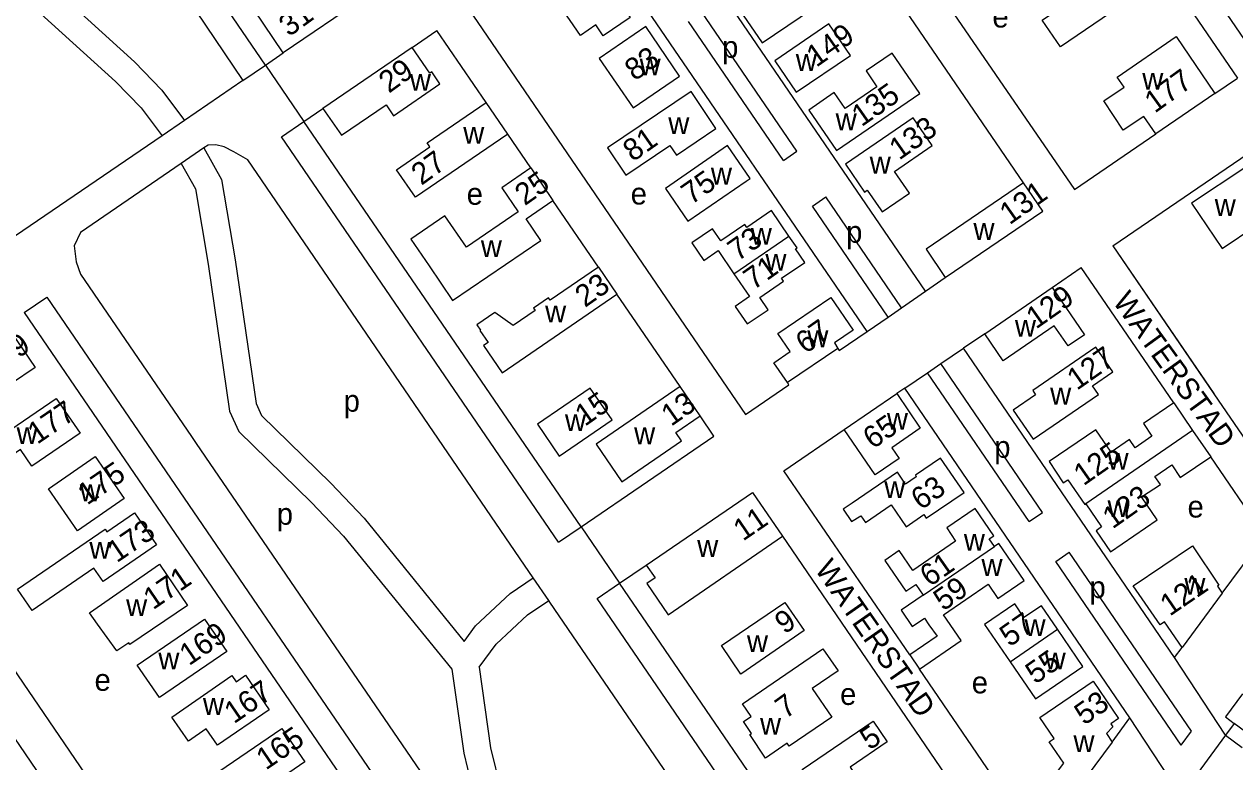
# Model space of a CAD drawing. Extents: x 154320 to 156262, y 382651 to 384180.
# Drawn here: x 155553.7 to 155775.5, y 383279.2 to 383414.4 of the extents above; entities that cross this region are included whole.
import ezdxf

# ---------------------------------------------------------------- set-up
doc = ezdxf.new("R2010")
doc.units = 0
for name, color, linetype in [('BLT_Basislijn', 7, 'Continuous'), ('BLT_Bebouwing', 7, 'Continuous'), ('BLT_Centroide', 7, 'Continuous'), ('BLT_Huisnummer', 7, 'Continuous'), ('BLT_Onderdoorgang_en_onderverdeling', 7, 'Continuous'), ('BLT_Onderverdeling_panden', 7, 'Continuous'), ('BLT_Straatnaam', 7, 'Continuous'), ('BLT_Vlakafsluiter', 7, 'Continuous')]:
    doc.layers.add(name, color=color, linetype=linetype)

msp = doc.modelspace()

# ---------------------------------------------------------------- linework, layer by layer
at = {"layer": 'BLT_Basislijn'}
for p, q in [((155556.64, 383458.99), (155593.76, 383404.06)), ((155695.34, 383458.35), (155746.12, 383384.05)), ((155736.8, 383385.3), (155689.56, 383454.4)), ((155718.85, 383365.44), (155668.08, 383439.72)), ((155708.13, 383358.08), (155657.35, 383432.39)), ((155635.07, 383417.16), (155685.86, 383342.86)), ((155692.79, 383389.39), (155675.38, 383414.87)), ((155695.26, 383391.09), (155677.85, 383416.57)), ((155624.76, 383410.11), (155629.29, 383413.21)), ((155638.32, 383400), (155629.29, 383413.21)), ((155597.88, 383406.88), (155601.13, 383409.09)), ((155593.76, 383404.06), (155597.88, 383406.88)), ((155593.76, 383404.06), (155583.05, 383396.74)), ((155771.89, 383401.67), (155776.01, 383404.48)), ((155604.94, 383396.56), (155608.42, 383398.94)), ((155583.05, 383396.74), (155578.92, 383393.92)), ((155600.81, 383393.74), (155604.94, 383396.56)), ((155646.52, 383388.04), (155642.27, 383394.22)), ((155746.12, 383384.05), (155761.04, 383394.24)), ((155753.18, 383373.73), (155783.06, 383394.16)), ((155586.6, 383391.69), (155582.46, 383388.85)), ((155692.79, 383389.39), (155695.26, 383391.09)), ((155658.91, 383369.87), (155650.54, 383382.07)), ((155698.11, 383381.01), (155700.59, 383382.7)), ((155714.46, 383362.41), (155700.59, 383382.7)), ((155711.98, 383360.71), (155698.11, 383381.01)), ((155742.04, 383366.09), (155747.4, 383369.78)), ((155764.34, 383344.99), (155747.4, 383369.78)), ((155718.85, 383365.44), (155722.45, 383367.93)), ((155553.66, 383361.51), (155557.79, 383364.33)), ((155673.9, 383347.96), (155662.3, 383364.91)), ((155714.46, 383362.41), (155718.85, 383365.44)), ((155711.98, 383360.71), (155714.46, 383362.41)), ((155708.13, 383358.08), (155711.98, 383360.71)), ((155729.69, 383357.65), (155725.79, 383355)), ((155721.66, 383352.19), (155725.79, 383355)), ((155764.5, 383298.35), (155725.79, 383355)), ((155715.05, 383347.68), (155719.18, 383350.49)), ((155719.18, 383350.49), (155721.66, 383352.19)), ((155737.82, 383323.22), (155719.18, 383350.49)), ((155740.3, 383324.91), (155721.66, 383352.19)), ((155715.05, 383347.68), (155713.56, 383346.67)), ((155756.32, 383287.28), (155715.05, 383347.68)), ((155772.5, 383345.46), (155785.39, 383326.61)), ((155680.08, 383338.91), (155677.56, 383342.59)), ((155521.89, 383339.79), (155585.65, 383246.5)), ((155692.91, 383332.54), (155703.92, 383340.08)), ((155655.72, 383322.26), (155680.08, 383338.91)), ((155516.11, 383335.84), (155555.91, 383277.62)), ((155780.99, 383320.63), (155771.12, 383335.1)), ((155715.98, 383298.81), (155692.91, 383332.54)), ((155737.82, 383323.22), (155740.3, 383324.91)), ((155651.6, 383319.44), (155655.72, 383322.26)), ((155692.64, 383320.53), (155725.53, 383272.42)), ((155773.24, 383310.1), (155780.99, 383320.63)), ((155742.71, 383315.9), (155745.19, 383317.6)), ((155767.6, 383284.81), (155745.19, 383317.6)), ((155662.78, 383311.94), (155667.63, 383315.26)), ((155765.7, 383282.27), (155742.71, 383315.9)), ((155649.79, 383308.8), (155646.96, 383312.92)), ((155658.65, 383309.12), (155662.78, 383311.94)), ((155764.5, 383298.35), (155765.88, 383300.16)), ((155773.85, 383284.08), (155764.5, 383298.35)), ((155734.58, 383271.59), (155717.76, 383296.2)), ((155753.04, 383282.83), (155756.32, 383287.28)), ((155765.68, 383273), (155756.32, 383287.28)), ((155765.7, 383282.27), (155767.6, 383284.81))]:
    msp.add_line(p, q, dxfattribs=at)
for points in [[(155473.87, 383522.91), (155483.98, 383497.86), (155486.36, 383493.38), (155496.62, 383477.01), (155506.99, 383465.16), (155518.91, 383453.74), (155544.48, 383433.68), (155554.14, 383425.4), (155573.89, 383407.44), (155578.88, 383402.26), (155583.05, 383396.74)], [(155724.46, 383488.76), (155778.83, 383409.21)], [(155725.22, 383478.78), (155776.01, 383404.48)], [(155597.88, 383406.88), (155561.52, 383460.08)], [(155541.74, 383429.44), (155550.83, 383421.65), (155570.4, 383403.86), (155575.07, 383399.01), (155578.92, 383393.92)], [(155655.72, 383322.26), (155604.94, 383396.56)], [(155578.92, 383393.92), (155550.74, 383374.65)], [(155651.6, 383319.44), (155600.81, 383393.74)], [(155609.37, 383367.92), (155594.62, 383389.51), (155592.08, 383390.99), (155590.31, 383391.9), (155588.78, 383392.23), (155587.35, 383392.2), (155586.6, 383391.69)], [(155586.6, 383391.69), (155589.84, 383385.89), (155592.33, 383371.19), (155596.16, 383344.88), (155597.14, 383342.68), (155609.88, 383330.25), (155615.94, 383323.87), (155634.31, 383301.29), (155636.39, 383304.12), (155642.75, 383310.08), (155646.96, 383312.92)], [(155582.46, 383388.85), (155564.01, 383376.22), (155562.83, 383373.73), (155563.17, 383370.79), (155563.98, 383368.57), (155584.31, 383338.82)], [(155582.46, 383388.85), (155585.05, 383384.2), (155587.39, 383370.41), (155591.31, 383343.47), (155592.97, 383339.76), (155606.32, 383326.74), (155612.19, 383320.57), (155632.03, 383296.17)], [(155753.18, 383373.73), (155771.67, 383346.67)], [(155753.18, 383373.73), (155772.5, 383345.46)], [(155645.38, 383315.25), (155609.37, 383367.92)], [(155557.79, 383364.33), (155621.56, 383271.05)], [(155553.66, 383361.51), (155617.43, 383268.23)], [(155702.78, 383354.92), (155703, 383354.57), (155708.13, 383358.08)], [(155685.86, 383342.86), (155693.81, 383348.29), (155693.53, 383348.7)], [(155584.31, 383338.82), (155585.2, 383337.53)], [(155585.2, 383337.53), (155633.64, 383266.67)], [(155646.96, 383312.92), (155645.38, 383315.25)], [(155703.78, 383251.95), (155662.78, 383311.94)], [(155637.02, 383296.55), (155640.14, 383300.78), (155645.88, 383306.16), (155649.79, 383308.8)], [(155650, 383308.48), (155649.79, 383308.8)], [(155733.58, 383186.21), (155650, 383308.48)], [(155743.62, 383184.81), (155658.65, 383309.12)], [(155632.03, 383296.17), (155634.22, 383280.82), (155636.28, 383272.35), (155637.06, 383270.79)], [(155637.02, 383296.55), (155639.14, 383281.76), (155641.01, 383274.08), (155641.67, 383272.76), (155645.83, 383270.38), (155656.73, 383261.45), (155664.48, 383253), (155671.55, 383242.34)]]:
    msp.add_lwpolyline(points, dxfattribs=at)
at = {"layer": 'BLT_Bebouwing'}
for p, q in [((155616.31, 383419.44), (155601.13, 383409.09)), ((155771.89, 383401.67), (155761.04, 383394.24)), ((155642.27, 383394.22), (155638.32, 383400)), ((155646.52, 383388.04), (155650.54, 383382.07)), ((155658.91, 383369.87), (155662.3, 383364.91)), ((155729.69, 383357.65), (155742.04, 383366.09)), ((155551.17, 383358.09), (155555.66, 383351.45)), ((155555.66, 383351.45), (155551.36, 383348.55)), ((155677.56, 383342.59), (155673.9, 383347.96)), ((155703.92, 383340.08), (155713.56, 383346.67)), ((155764.34, 383344.99), (155767.79, 383339.94)), ((155767.79, 383339.94), (155771.12, 383335.1)), ((155667.63, 383315.26), (155687.13, 383328.59)), ((155565.61, 383306.49), (155578.47, 383315.46)), ((155578.47, 383315.46), (155583.56, 383307.88)), ((155773.24, 383310.1), (155765.88, 383300.16)), ((155567.09, 383304.46), (155565.61, 383306.49)), ((155583.56, 383307.88), (155573, 383300.73)), ((155570.66, 383299.53), (155567.09, 383304.46)), ((155715.98, 383298.81), (155717.76, 383296.2)), ((155775.43, 383286.24), (155773.85, 383284.08)), ((155773.85, 383284.08), (155765.68, 383273)), ((155753.04, 383282.83), (155739.44, 383264.48))]:
    msp.add_line(p, q, dxfattribs=at)
for points in [[(155697.78, 383427.86), (155693.81, 383425.08), (155695.35, 383422.82), (155685.43, 383416.04), (155688.91, 383410.93), (155702.86, 383420.43)], [(155740.22, 383415.12), (155755.49, 383425.56), (155758.85, 383420.64), (155743.58, 383410.2)], [(155667.56, 383413.91), (155659.05, 383408.1), (155665.26, 383399.02), (155673.76, 383404.83)], [(155705.07, 383408.64), (155701.13, 383414.42), (155691.22, 383407.67), (155695.17, 383401.89)], [(155717.79, 383401.63), (155712.71, 383409.05), (155707.95, 383405.8), (155709.95, 383402.87), (155704.13, 383398.91), (155704.1, 383398.89), (155702.11, 383401.82), (155697.45, 383398.62), (155702.54, 383391.19)], [(155675.88, 383402.02), (155660.55, 383391.69), (155663.91, 383386.71), (155671.99, 383392.15), (155673.18, 383390.39), (155680.41, 383395.26)], [(155716.61, 383397.2), (155704.19, 383388.7), (155707.66, 383383.61), (155708.18, 383383.97), (155710.67, 383380.33), (155710.91, 383379.98), (155715.91, 383383.4), (155713.19, 383387.4), (155720.09, 383392.12)], [(155671.17, 383384.28), (155671.17, 383384.28), (155675.29, 383378.29), (155685.96, 383385.61), (155686.69, 383386.11), (155682.57, 383392.11)], [(155777.52, 383388.19), (155767.61, 383381.54), (155773.21, 383373.26), (155785.57, 383381.57), (155781.34, 383387.77), (155778.94, 383386.11)], [(155750.04, 383355.17), (155738.52, 383347.23), (155739.02, 383346.48), (155734.93, 383343.67), (155738.59, 383338.35), (155750.54, 383346.53), (155749.46, 383348.09), (155753.15, 383350.64)], [(155651.7, 383335.24), (155661.39, 383341.85), (155657.41, 383347.68), (155647.72, 383341.06)], [(155559.55, 383345.79), (155563.92, 383339.45), (155555.04, 383333.38), (155552.97, 383336.41), (155548.57, 383333.47), (155546.31, 383336.79)], [(155725.91, 383328.55), (155721.58, 383334.86), (155716.98, 383331.73), (155717.16, 383331.46), (155715.16, 383330.09), (155713.69, 383332.26), (155705.4, 383326.62), (155703.74, 383325.49), (155705.29, 383323.22), (155706.97, 383324.31), (155707.84, 383323.04), (155712.57, 383326.27), (155715.27, 383322.29), (155718.54, 383324.52), (155718.99, 383323.85)], [(155552.46, 383310.85), (155568.52, 383321.84), (155568.52, 383321.84), (155568.83, 383321.38), (155573.89, 383324.84), (155577.93, 383318.97), (155568.15, 383312.27), (155566.45, 383314.72), (155555.11, 383306.97)], [(155681.48, 383300.53), (155693.05, 383308.42), (155696.61, 383303.25), (155684.99, 383295.29)], [(155578.45, 383291.01), (155574.38, 383296.93), (155586.72, 383305.37), (155590.81, 383299.42)], [(155700.05, 383299.93), (155702.81, 383295.89), (155698.07, 383292.65), (155701.66, 383287.4), (155693.88, 383282.08), (155693.51, 383282.62), (155689.55, 383279.91), (155686.62, 383284.21), (155686.95, 383284.43), (155685.48, 383286.58), (155686.88, 383287.54), (155685.3, 383289.85)], [(155580.71, 383287.42), (155591.71, 383295.01), (155592.49, 383293.88), (155594.25, 383295.08), (155598.54, 383288.77), (155589.08, 383282.24), (155587, 383285.26), (155583.8, 383283.03)], [(155693.07, 383274.69), (155696.7, 383277.17), (155696.26, 383277.81), (155709.26, 383286.67), (155711.83, 383282.87), (155705.05, 383278.22), (155707.15, 383275.12), (155697.37, 383268.44)], [(155588.19, 383276.62), (155600.89, 383285.34), (155605.09, 383279.22), (155592.39, 383270.5)]]:
    msp.add_lwpolyline(points, close=True, dxfattribs=at)
for points in [[(155601.13, 383409.09), (155595.78, 383416.98), (155604.04, 383422.64), (155606.48, 383419.06), (155613.38, 383423.78), (155616.31, 383419.44)], [(155659.87, 383422.81), (155664.73, 383415.61), (155659.79, 383412.24), (155658.41, 383414.23), (155655.62, 383412.27), (155651.85, 383417.77)], [(155761.04, 383394.24), (155758.84, 383397.45), (155755.09, 383394.96), (155751.53, 383400.31), (155755.26, 383402.79), (155753.97, 383404.67), (155764.79, 383412.11), (155771.89, 383401.67)], [(155624.76, 383410.11), (155608.42, 383398.94)], [(155611.8, 383394.01), (155619.97, 383399.59), (155621.34, 383397.59), (155629.86, 383403.42), (155628.37, 383405.61), (155628.01, 383405.36), (155624.76, 383410.11)], [(155771.89, 383401.67), (155761.04, 383394.24)], [(155642.27, 383394.22), (155642.27, 383394.22), (155625.35, 383382.65), (155621.9, 383387.69), (155628.01, 383391.86), (155627.51, 383392.61), (155638.32, 383400)], [(155608.42, 383398.94), (155611.8, 383394.01)], [(155646.52, 383388.04), (155641.2, 383384.4), (155644.21, 383379.98), (155634.7, 383373.48), (155630.74, 383379.26), (155624.5, 383374.99), (155627.86, 383370.1), (155632.18, 383363.75), (155632.18, 383363.75), (155648.35, 383374.74), (155645.64, 383378.69), (155650.54, 383382.07)], [(155736.8, 383385.3), (155718.99, 383373.13), (155722.45, 383367.93)], [(155722.45, 383367.93), (155740.35, 383380.13), (155736.8, 383385.3)], [(155693.82, 383375.52), (155690.62, 383380.2), (155686.08, 383377.1), (155685.71, 383377.64), (155681.36, 383374.67), (155679.83, 383376.89), (155676, 383374.29), (155678.21, 383371.08), (155680.83, 383372.87), (155683.71, 383368.64)], [(155683.71, 383368.64), (155686.57, 383364.44), (155683.96, 383362.65), (155686.16, 383359.44), (155689.99, 383362.04), (155688.46, 383364.27), (155692.81, 383367.26), (155692.45, 383367.81), (155696.71, 383370.71), (155695.03, 383373.19), (155695.3, 383373.37), (155693.82, 383375.52)], [(155658.91, 383369.87), (155650.05, 383363.81), (155649.77, 383364.23), (155647.01, 383362.35), (155647.01, 383362.35), (155647.3, 383361.93), (155643.29, 383359.18), (155639.89, 383361.52), (155636.64, 383359.3), (155637.28, 383358.33), (155637.15, 383358.24), (155638.67, 383356.03), (155637.85, 383355.47), (155641.23, 383350.51), (155662.3, 383364.91)], [(155742.04, 383366.09), (155747.96, 383357.43), (155744.99, 383355.41), (155742.45, 383359.1), (155733.06, 383352.69), (155729.69, 383357.65)], [(155693.53, 383348.7), (155691.05, 383352.33), (155694.05, 383354.38), (155691.79, 383357.69), (155701.47, 383364.31), (155705.58, 383358.3), (155702.14, 383355.95), (155702.78, 383354.92)], [(155702.78, 383354.92), (155693.53, 383348.7)], [(155673.9, 383347.96), (155658.48, 383337.4), (155663.19, 383330.53), (155674.13, 383338), (155673.08, 383339.53), (155677.56, 383342.59)], [(155713.56, 383346.67), (155717.88, 383340.32), (155712.69, 383336.77), (155714.02, 383334.81), (155709.6, 383331.78), (155703.92, 383340.08)], [(155764.34, 383344.99), (155758.77, 383341.19), (155760.35, 383338.87), (155757.25, 383336.75), (155756.22, 383338.25), (155752.85, 383335.92), (155750.04, 383340.05), (155741.48, 383334.21), (155744.09, 383330.33), (155744.92, 383330.89), (155748.04, 383326.35), (155748.21, 383326.47)], [(155558.12, 383329.25), (155566.67, 383335.16), (155571.98, 383327.47)], [(155748.21, 383326.47), (155751.11, 383322.24), (155750.11, 383321.55), (155752.75, 383317.69), (155761.32, 383323.56), (155758.45, 383327.74), (155761.89, 383330), (155760.87, 383331.48), (155763.97, 383333.6), (155765.54, 383331.29), (155771.12, 383335.1)], [(155571.98, 383327.47), (155563.41, 383321.56), (155558.12, 383329.25)], [(155687.13, 383328.59), (155692.64, 383320.53)], [(155731.48, 383318.66), (155730.51, 383320.08), (155731.34, 383320.63), (155727.94, 383325.61), (155722.73, 383322.06), (155724.37, 383319.65), (155716.52, 383314.29), (155716.52, 383314.29), (155714.03, 383317.92), (155711.38, 383316.1), (155715.23, 383310.48), (155717.05, 383311.73), (155718.41, 383309.74)], [(155667.63, 383315.26), (155669.27, 383312.93), (155667.8, 383311.9), (155671.69, 383306.17), (155692.64, 383320.53)], [(155717.76, 383296.2), (155725.38, 383301.43), (155722.14, 383306.17), (155730.3, 383311.75), (155732.08, 383309.16), (155736.95, 383312.44), (155732.3, 383319.22), (155731.48, 383318.66)], [(155765.88, 383300.16), (155762.66, 383304.86), (155761.82, 383304.29), (155756.92, 383311.46), (155767.79, 383318.76), (155772.62, 383311.57), (155772.35, 383311.39), (155773.24, 383310.1)], [(155718.41, 383309.74), (155714.37, 383307), (155716.43, 383304.03), (155718.64, 383305.54), (155719.46, 383304.34), (155720.97, 383302.21), (155715.98, 383298.81)], [(155743.04, 383303.5), (155740.09, 383307.82), (155736.89, 383305.65), (155735.2, 383308.16), (155729.68, 383304.39), (155734.33, 383297.56)], [(155734.33, 383297.56), (155738.98, 383290.74), (155747.68, 383296.68), (155743.04, 383303.5)], [(155573, 383300.73), (155572.84, 383301.01), (155570.66, 383299.53)], [(155734.58, 383271.59), (155742.87, 383277.18), (155744.17, 383279), (155741.52, 383282.89), (155742.43, 383283.52), (155739.81, 383287.34), (155749.57, 383293.99), (155754.23, 383287.14), (155752.82, 383286.19), (155753.19, 383285.64), (155751.99, 383284.39), (155753.04, 383282.83)], [(155776.95, 383291.65), (155773.82, 383287.43), (155775.43, 383286.24)]]:
    msp.add_lwpolyline(points, dxfattribs=at)
at = {"layer": 'BLT_Onderdoorgang_en_onderverdeling'}
msp.add_line((155773.85, 383284.08), (155776.89, 383281.82), dxfattribs=at)
at = {"layer": 'BLT_Onderverdeling_panden'}
for p, q in [((155683.71, 383368.64), (155693.82, 383375.52)), ((155767.79, 383339.94), (155748.21, 383326.47)), ((155718.41, 383309.74), (155731.48, 383318.66)), ((155734.33, 383297.56), (155743.04, 383303.5)), ((155783.51, 383280.27), (155775.43, 383286.24))]:
    msp.add_line(p, q, dxfattribs=at)
at = {"layer": 'BLT_Vlakafsluiter'}
for p, q in [((155597.88, 383406.88), (155604.94, 383396.56)), ((155655.72, 383322.26), (155662.78, 383311.94))]:
    msp.add_line(p, q, dxfattribs=at)

# ---------------------------------------------------------------- texts
at = {"layer": 'BLT_Centroide'}
for s, p in [('e', (155731.11, 383413.75)), ('p', (155681.57, 383408.18)), ('w', (155666.45, 383405)), ('w', (155695.08, 383405.8)), ('w', (155624.34, 383402.15)), ('w', (155758.57, 383402.35)), ('w', (155671.7, 383394.21)), ('w', (155702.38, 383394.93)), ('w', (155634.12, 383392.47)), ('w', (155708.62, 383386.99)), ('w', (155679.51, 383384.97)), ('e', (155634.76, 383381.28)), ('e', (155664.82, 383381.32)), ('w', (155686.83, 383373.97)), ('p', (155704.3, 383374.31)), ('w', (155727.63, 383374.84)), ('w', (155637.35, 383371.69)), ('w', (155689.5, 383369.19)), ('w', (155649.13, 383359.74)), ('w', (155735.23, 383357.09)), ('w', (155697.17, 383355.17)), ('p', (155612.21, 383343.36)), ('w', (155741.69, 383344.68)), ('w', (155652.77, 383339.8)), ('w', (155711.77, 383340.08)), ('w', (155552.27, 383337.45)), ('w', (155665.44, 383337.41)), ('p', (155731.45, 383334.91)), ('w', (155752.2, 383332.74)), ('w', (155711.29, 383327.53)), ('w', (155563.85, 383326.97)), ('w', (155752.2, 383324.08)), ('e', (155766.87, 383323.97)), ('p', (155599.95, 383322.64)), ('w', (155565.61, 383316.42)), ('w', (155677, 383316.77)), ('w', (155725.87, 383317.91)), ('w', (155729.1, 383313.28)), ('w', (155766.28, 383309.82)), ('p', (155748.9, 383309.21)), ('w', (155572.34, 383305.92)), ('w', (155736.99, 383302.25)), ('w', (155686.12, 383299.31)), ('w', (155578.25, 383296.15)), ('w', (155740.69, 383296.17)), ('e', (155727.32, 383291.76)), ('e', (155703.19, 383289.64)), ('w', (155586.42, 383287.81)), ('w', (155688.52, 383284.2)), ('w', (155745.96, 383281.01))]:
    msp.add_text(s, height=4, dxfattribs=at).set_placement(p)
for s, p in [('w', (155771.83, 383379.25)), ('e', (155566.54, 383292.24))]:
    msp.add_text(s, height=4, rotation=359.5, dxfattribs=at).set_placement(p)
at = {"layer": 'BLT_Huisnummer'}
for s, rotation, p in [('31', 35.8967, (155602.2, 383411.94)), ('149', 35.0638, (155698.83, 383406.36)), ('83', 35.0638, (155665.53, 383403.85)), ('29', 35.8967, (155620.5, 383401.6)), ('177', 35.8967, (155760.86, 383397.95)), ('135', 35.0638, (155707.12, 383395.46)), ('133', 35.0638, (155714.01, 383389.34)), ('81', 35.0638, (155665.21, 383389.05)), ('27', 35.8967, (155626.46, 383384.72)), ('25', 35.0638, (155645.4, 383381)), ('75', 35.0638, (155675.9, 383381.17)), ('131', 35.0638, (155734.24, 383377.5)), ('73', 35.0638, (155684.41, 383370.81)), ('71', 35.0638, (155687.3, 383365.54)), ('23', 35.0638, (155656.43, 383362.35)), ('129', 35.0638, (155739.1, 383358.4)), ('67', 35.0638, (155696.84, 383353.85)), ('179', 34.3539, (155547.73, 383349.74)), ('127', 35.0638, (155746.59, 383347.17)), ('15', 35.0638, (155656.42, 383340.57)), ('13', 35.0638, (155672.22, 383340.57)), ('177', 34.3542, (155556.05, 383337.29)), ('65', 35.0638, (155709.2, 383336.4)), ('125', 35.0638, (155747.8, 383329.68)), ('175', 34.3538, (155565.19, 383326.14)), ('63', 35.0638, (155717.99, 383325.22)), ('123', 35.0638, (155753.11, 383321.77)), ('11', 34.3525, (155685.39, 383319.55)), ('173', 34.2929, (155570.63, 383315.58)), ('61', 35.0638, (155719.62, 383311.17)), ('171', 34.3538, (155577.27, 383306.96)), ('59', 35.0638, (155722.11, 383306.73)), ('121', 34.4, (155763.6, 383305.79)), ('9', 34.3525, (155692.99, 383302.5)), ('57', 35.0638, (155734.25, 383300.16)), ('169', 34.3539, (155583.87, 383296.72)), ('55', 35.0638, (155738.97, 383293.32)), ('167', 34.3539, (155592.09, 383286.08)), ('7', 35.8967, (155693.17, 383286.98)), ('53', 35.0638, (155747.94, 383285.8)), ('165', 34.3539, (155597.95, 383277.6)), ('5', 34.3525, (155708.6, 383281.25))]:
    msp.add_text(s, height=4, rotation=rotation, dxfattribs=at).set_placement(p)
at = {"layer": 'BLT_Straatnaam'}
for rotation, p in [(305.8967, (155753, 383363.53)), (304.8967, (155698.42, 383314.5))]:
    msp.add_text('WATERSTAD', height=4, rotation=rotation, dxfattribs=at).set_placement(p)

doc.saveas('drawing.dxf')
